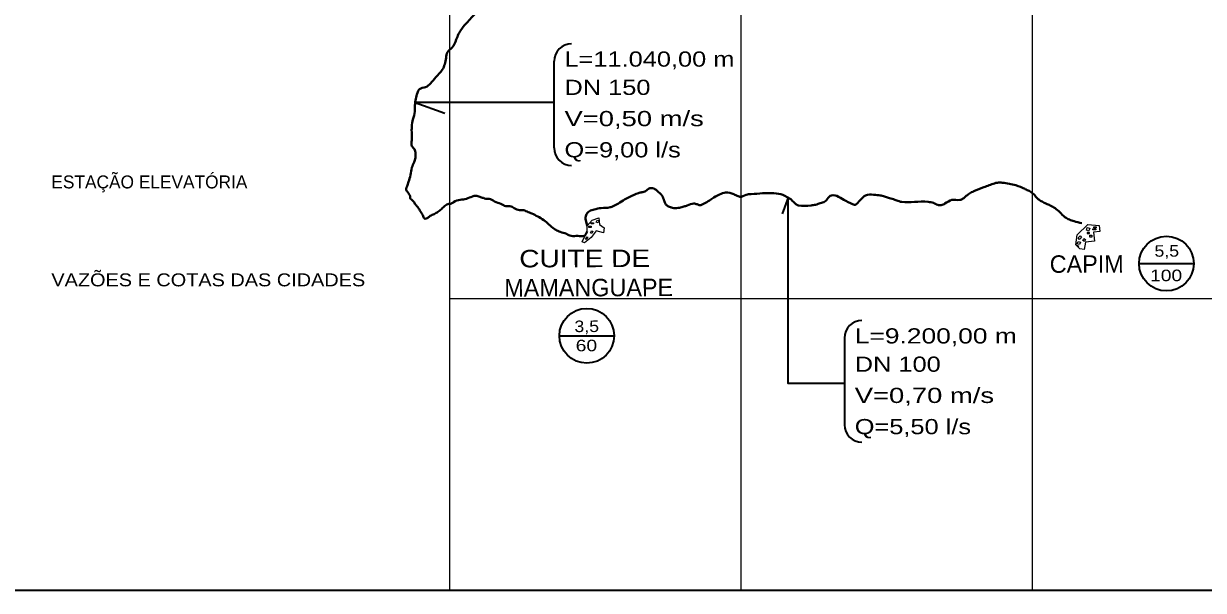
# Model space of a CAD drawing. Extents: x 0 to 1682, y 0 to 1188.
# Drawn here: x 1241.3 to 1499.4, y 427.1 to 551 of the extents above; entities that cross this region are included whole.
import ezdxf
from ezdxf.enums import TextEntityAlignment as Align

# ---------------------------------------------------------------- set-up
doc = ezdxf.new("R2010")
doc.units = 0
doc.header["$LTSCALE"] = 1.3
doc.linetypes.add('DOT_DASHED', pattern=[7.7, 5, -1.2, 0.3, -1.2])
for name, color, linetype, lineweight in [('1', 7, 'DOT_DASHED', 13), ('6', 7, 'Continuous', 40), ('63', 7, 'Continuous', 25), ('8', 7, 'Continuous', 35), ('9', 7, 'Continuous', 40)]:
    doc.layers.add(name, color=color, linetype=linetype, lineweight=lineweight)

msp = doc.modelspace()

# ---------------------------------------------------------------- linework, layer by layer
at = {"layer": '1', "linetype": 'Continuous'}
for points in [[(1363.497, 503.293), (1364.644, 505.542), (1364.608, 506.841), (1365.71, 508.015), (1367.134, 508.548), (1367.283, 507.089), (1368.326, 506.338), (1368.201, 505.248), (1366.566, 505.708), (1365.465, 504.293), (1364.027, 503.118)], [(1364.994, 506.473), (1364.993, 506.7), (1365.49, 506.701), (1365.49, 506.474)], [(1365.456, 507.26), (1365.455, 507.487), (1365.984, 507.488), (1365.985, 507.262)], [(1366.592, 507.632), (1366.783, 508.066), (1367.217, 507.875), (1367.026, 507.441)], [(1473.807, 505.843), (1473.966, 506.421), (1474.545, 506.262), (1474.385, 505.683)], [(1475.203, 505.941), (1475.202, 506.156), (1475.901, 506.158), (1475.901, 505.943)], [(1475.417, 506.345), (1475.416, 506.56), (1475.94, 506.562), (1475.94, 506.347)], [(1364.393, 503.841), (1364.232, 504.001), (1364.6, 504.37), (1364.761, 504.21)], [(1365.334, 505.255), (1365.541, 505.737), (1365.838, 505.609), (1365.632, 505.127)], [(1471.829, 502.907), (1471.988, 503.418), (1472.499, 503.258), (1472.34, 502.747)], [(1471.986, 504.184), (1472.455, 504.589), (1472.769, 504.225), (1472.3, 503.82)], [(1473.048, 503.636), (1473.275, 504.013), (1473.652, 503.786), (1473.425, 503.409)], [(1473.97, 505.104), (1474.521, 505.106), (1474.52, 505.361), (1473.97, 505.359)], [(1474.577, 504.34), (1474.575, 504.797), (1475.032, 504.798), (1475.034, 504.341)]]:
    msp.add_lwpolyline(points, close=True, dxfattribs=at)
msp.add_lwpolyline([(1472.247, 502.298), (1471.494, 502.685), (1471.803, 504.873), (1474.151, 507.091), (1476.603, 506.904), (1476.753, 505.543), (1475.392, 505.394), (1475.609, 503.427), (1473.641, 503.21), (1473.317, 501.621), (1472.395, 501.809), (1471.494, 502.685)], dxfattribs=at)
at = {"layer": '6'}
for p, q in [((1428.915, 513.458), (1428.739, 513.463)), ((1364.24, 508.356), (1364.608, 506.841))]:
    msp.add_line(p, q, dxfattribs=at)
for points in [[(1344.512, 579.355), (1347.048, 574.056), (1346.78, 572.547), (1346.379, 572.04), (1345.8, 571.314), (1345.026, 570.476), (1344.171, 569.379), (1343.481, 568.211), (1342.778, 567.15), (1342.241, 566.065), (1341.62, 565.074), (1341.058, 564.26), (1341.06, 563.848), (1341.215, 562.824), (1341.371, 562.06), (1342.073, 559.724), (1343.192, 557.666), (1342.723, 556.55), (1340.533, 553.647), (1338.481, 551.412), (1337.178, 549.876), (1335.96, 547.505), (1335.047, 545.719), (1334.076, 544.769), (1333.746, 543.487), (1332.919, 540.922), (1331.505, 539.274), (1330.343, 537.913), (1329.279, 537.109), (1327.927, 536.694), (1327.478, 535.851), (1327.134, 534.536), (1326.933, 533.119), (1326.937, 531.771), (1326.511, 530.038), (1326.249, 528.518), (1326.254, 526.896), (1326.258, 525.549), (1326.262, 524.201), (1326.838, 523.572), (1327.067, 522.587), (1327.069, 521.684), (1326.754, 520.698), (1326.278, 519.543), (1325.997, 517.931), (1325.534, 516.421), (1325.217, 515.461), (1325.014, 514.866), (1325.289, 514.238), (1325.921, 513.075), (1325.921, 512.869), (1326.516, 512.265), (1326.918, 511.649), (1327.456, 511.011), (1327.907, 510.369), (1328.43, 509.539), (1328.83, 508.733), (1329.041, 508.411), (1329.785, 508.587), (1330.279, 508.961), (1331.171, 509.386), (1331.975, 509.884), (1332.742, 510.482), (1333.484, 511.167), (1334.338, 511.592), (1334.71, 511.593), (1335.357, 511.979), (1336.869, 512.473), (1338.208, 512.745), (1339.499, 513.215), (1340.255, 513.392), (1341.106, 513.127), (1341.91, 512.908)], [(1460.352, 514.879), (1458.358, 515.675), (1456.963, 515.991), (1455.414, 516.233), (1454.338, 516.229), (1453.149, 515.9), (1451.93, 515.459), (1451.373, 515.222), (1449.202, 514.387), (1448.247, 513.846), (1447.513, 513.333), (1447.001, 512.881), (1446.481, 512.577), (1446.147, 512.47), (1444.38, 512.465), (1442.882, 511.679), (1442.038, 511.338), (1441.299, 511.407), (1440.377, 511.801), (1439.206, 512.047), (1436.202, 512.038), (1433.415, 512.03), (1432.829, 512.166), (1431.945, 512.501), (1430.731, 512.885), (1429.906, 513.151), (1428.915, 513.458)], [(1383.076, 510.825), (1382.238, 511.127), (1381.751, 511.612), (1381.476, 512.271), (1381.006, 513.382), (1379.936, 514.434), (1378.89, 515.068), (1377.78, 514.735), (1377.38, 514.4), (1376.591, 514.137), (1375.834, 513.974), (1373.924, 513.111), (1372.815, 512.571), (1371.448, 511.695), (1370.328, 511.089), (1369.648, 510.86), (1367.666, 510.683), (1366.174, 510.394), (1365.124, 510.026), (1364.479, 509.376), (1364.239, 508.354)], [(1428.739, 513.463), (1427.282, 513.605), (1425.522, 513.467), (1424.505, 512.597), (1423.566, 511.601), (1423.226, 511.395), (1423.098, 511.394), (1422.668, 511.542), (1420.771, 512.496), (1419.199, 513.343), (1417.76, 513.339), (1416.937, 512.406), (1416.62, 512.094), (1416.084, 511.875), (1415.113, 511.603), (1414.546, 511.414), (1413.577, 511.283), (1410.865, 511.275), (1410.401, 511.461), (1409.809, 511.977), (1409.154, 512.604), (1408.504, 513), (1407.444, 513.547), (1405.48, 513.955), (1400.508, 513.739), (1399.373, 513.589), (1398.029, 513.147), (1397.648, 513.257), (1396.672, 513.722), (1394.893, 514.104), (1393.568, 513.647), (1391.905, 512.728), (1389.625, 511.386), (1389.303, 511.31), (1388.655, 511.508), (1387.952, 511.682), (1386.506, 511.248), (1385.782, 511.031), (1384.811, 510.777), (1383.56, 510.689), (1383.011, 510.839)], [(1472.814, 507.391), (1471.107, 507.825), (1470.096, 508.181), (1469.132, 508.734), (1468.005, 509.761), (1466.951, 510.661), (1465.908, 511.267), (1465.056, 511.642), (1464.138, 512.105), (1463.41, 512.534), (1462.884, 513.03), (1462.101, 513.897), (1461.274, 514.422), (1460.405, 514.845)], [(1341.91, 512.908), (1342.448, 512.737), (1343.143, 512.739), (1344.342, 512.135), (1345.748, 511.592), (1346.844, 511.122), (1347.731, 511.124), (1348.619, 510.698), (1349.803, 510.243), (1350.468, 510.245), (1351.471, 509.918), (1352.542, 509.47), (1353.807, 508.867), (1355.112, 508.07), (1356.249, 507.106), (1357.374, 506.167), (1358.226, 505.705), (1358.736, 505.489), (1360.06, 505.056), (1361.111, 504.595), (1362.597, 504.6), (1363.945, 504.604), (1364.644, 505.542)]]:
    msp.add_spline(points, degree=3, dxfattribs=at)
at = {"layer": '63', "lineweight": 13}
for p, q in [((1334.586, 427.142), (1334.586, 783.93)), ((1398.298, 427.142), (1398.298, 783.93)), ((1462.011, 427.142), (1462.011, 783.93)), ((1640.404, 490.855), (1334.586, 490.855))]:
    msp.add_line(p, q, dxfattribs=at)
at = {"layer": '63', "lineweight": 35}
msp.add_lwpolyline([(1640.404, 427.142), (952.314, 427.142), (952.314, 783.93)], dxfattribs=at)
at = {"layer": '8'}
for p, q in [((1357.397, 523.829), (1357.397, 542.785)), ((1420.895, 482.289), (1420.895, 463.333))]:
    msp.add_line(p, q, dxfattribs=at)
for points in [[(1357.397, 533.786), (1327.011, 533.786), (1333.459, 531.414)], [(1420.895, 472.332), (1408.546, 472.332), (1408.546, 512.982), (1407.279, 509.416)]]:
    msp.add_lwpolyline(points, dxfattribs=at)
for centre, start, end in [((1361.22, 542.785), 90, 180), ((1361.22, 542.785), 90, 180), ((1361.22, 542.785), 90, 180), ((1361.22, 523.829), 180, 270), ((1424.718, 482.289), 90, 180), ((1424.718, 463.333), 180, 270), ((1424.718, 463.333), 180, 270), ((1424.718, 463.333), 180, 270)]:
    msp.add_arc(centre, 3.823, start, end, dxfattribs=at)
at = {"layer": '9', "lineweight": 35}
for p, q in [((1485.334, 498.558), (1497.305, 498.558)), ((1358.529, 482.776), (1370.499, 482.776))]:
    msp.add_line(p, q, dxfattribs=at)
for centre in [(1491.319, 498.558), (1364.514, 482.776)]:
    msp.add_circle(centre, 5.985, dxfattribs=at)

# ---------------------------------------------------------------- texts
at = {"layer": '63'}
msp.add_text('ESTAÇÃO ELEVATÓRIA', height=2.829, dxfattribs=at).set_placement((1247.409, 514.987))
at = {"layer": '63', "width": 1.15}
msp.add_text('VAZÕES E COTAS DAS CIDADES', height=2.829, dxfattribs=at).set_placement((1247.409, 493.586))
at = {"layer": '8'}
for s, width, p in [('L=11.040,00 m', 1.25, (1359.649, 541.593)), ('DN 150', 1.25, (1359.649, 535.413)), ('V=0,50 m/s', 1.35, (1359.649, 528.59)), ('Q=9,00 l/s', 1.25, (1359.649, 521.766)), ('L=9.200,00 m', 1.3, (1423.147, 481.097)), ('DN 100', 1.25, (1423.147, 474.917)), ('V=0,70 m/s', 1.35, (1423.147, 468.094)), ('Q=5,50 l/s', 1.25, (1423.147, 461.27))]:
    msp.add_text(s, height=3.319, dxfattribs=dict(at, width=width)).set_placement(p)
at = {"layer": '9'}
for s, height, width, p in [('CUITE DE ', 3.823, 1.2, (1364.933, 497.771)), ('5,5', 2.52, 1.15, (1491.403, 500.066)), ('100', 2.52, 1.25, (1491.255, 494.708)), ('3,5', 2.52, 1.15, (1364.524, 483.596)), ('60', 2.52, 1.25, (1364.45, 479.393))]:
    msp.add_text(s, height=height, rotation=0.17, dxfattribs=dict(at, width=width)).set_placement(p, align=Align.CENTER)
msp.add_text('CAPIM', height=3.823, rotation=0.17, dxfattribs=at).set_placement((1465.799, 496.529))
msp.add_text('MAMANGUAPE', height=3.823, rotation=0.17, dxfattribs=at).set_placement((1364.952, 491.399), align=Align.CENTER)

doc.saveas('drawing.dxf')
